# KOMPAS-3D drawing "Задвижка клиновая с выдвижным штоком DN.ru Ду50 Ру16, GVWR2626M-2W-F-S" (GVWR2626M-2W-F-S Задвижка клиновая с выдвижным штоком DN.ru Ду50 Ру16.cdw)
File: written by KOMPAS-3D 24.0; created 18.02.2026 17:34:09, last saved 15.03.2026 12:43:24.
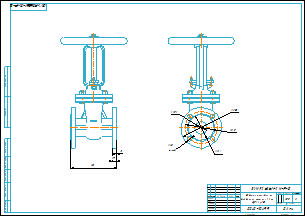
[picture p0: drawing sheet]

Document properties: Автор: R2D2; Форматы листов документа: A2; Полное имя файла: GVWR2626M-2W-F-S Задвижка клиновая с выдвижным штоком DN.ru Ду50 Ру16.m3d; Масса: 15.5; Наименование: Задвижка клиновая с выдвижным штоком DN.ru Ду50 Ру16; Количество листов документа: 1; Примечание: D040-10499

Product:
- Part/product: Задвижка клиновая с выдвижным штоком DN.ru Ду50 Ру16  | designation GVWR2626M-2W-F-S
    Масса: 15.5
    Раздел спецификации: Прочие изделия
    Примечание: D040-10499

Views: Проекционный вид 2
Referenced files in E:\Работа\Зайцев\GVWR2626M-2W-F-S Задвижка клиновая с выдвижным штоком DN.ru Ду50-300 Ру16\DN50\: GVWR2626M-2W-F-S Задвижка клиновая с выдвижным штоком DN.ru Ду50 Ру16.m3d
Referenced files in E:\Работа\Зайцев\Для компаса\: чертеж DN.ru А3.cdt
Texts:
  GVWR2626M-2W-F-S
  чертеж DN.ru А3.cdt
  Задвижка клиновая с
  выдвижным штоком DN.ru
  Ду50 Ру16
  Задвижка клиновая с выдвижным штоком DN.ru Ду50 Ру16
  GVWR2626M-2W-F-S Задвижка клиновая с выдвижным штоком DN.ru Ду50 Ру16
Dimensions and other numbers on the sheet: 0; 3; 4; 160; 125; 50; 102; 18; 4 отв.; 1:2; 1; 2; 15,5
